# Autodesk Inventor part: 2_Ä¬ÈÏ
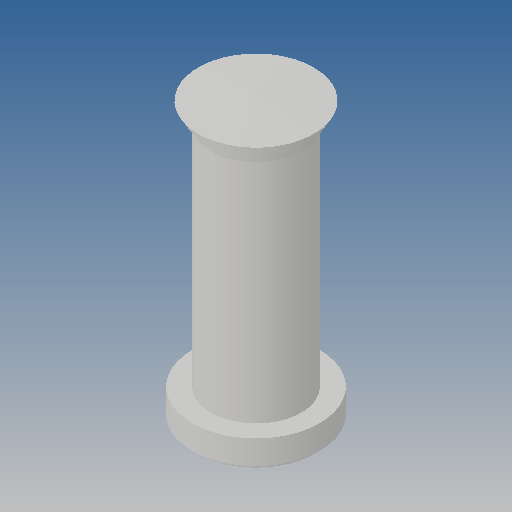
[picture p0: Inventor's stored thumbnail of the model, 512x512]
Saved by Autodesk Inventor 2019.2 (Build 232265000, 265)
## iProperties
Created: 2010-06
Part Number: 2_Ä¬ÈÏ
Material: Ogólny
Document SubType Name: Modeling
Designer: CADENGINEERING4
Density: 1 g/cm^3
Appearance: Domyślna
Author: CADENGINEERING4
Revision Number: ÈÎºÎ
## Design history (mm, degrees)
feature "NONE"
node "Bryła1"
